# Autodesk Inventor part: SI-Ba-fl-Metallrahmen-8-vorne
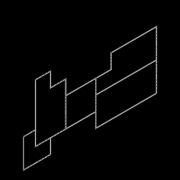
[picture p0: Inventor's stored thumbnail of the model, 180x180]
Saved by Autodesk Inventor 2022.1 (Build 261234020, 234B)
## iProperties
Created: 2021-12
Part Number: SI-Ba-fl-Metallrahmen-8-vorne
Material: Generisch
Document SubType Name: Modeling
Designer: Ruhl
Density: 1 g/cm^3
Appearance: Vorgabe
Author: Ruhl
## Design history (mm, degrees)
sketch "Skizze1"
  geometry: L1 (0, 0)-(-412, 0); L2 (-412, 0)-(-412, 210); L3 (-412, 210)-(-1052, 210); L4 (-1052, 210)-(-1052, 0); L5 (-1052, 0)-(-1952, 0); L6 (-1952, 0)-(-1952, 860); L7 (-1952, 860)-(-1272, 860); L8 (-1272, 860)-(-1272, 650); L9 (-1272, 650)-(-632, 650); L10 (-632, 650)-(-632, 860); L11 (-632, 860)-(-412, 860); L12 (-412, 860)-(-412, 1070); L13 (-412, 1070)-(-172, 1070); L14 (-172, 1070)-(-172, 440); L15 (-172, 440)-(0, 440); L16 (0, 440)-(0, 0); L17 (-192, 420)-(-192, 1050); L18 (-192, 1050)-(-392, 1050); L19 (-392, 1050)-(-392, 840); L20 (-392, 840)-(-612, 840); L21 (-612, 840)-(-612, 630); L22 (-612, 630)-(-1292, 630); L23 (-1292, 630)-(-1292, 840); L24 (-1292, 840)-(-1932, 840); L25 (-1932, 840)-(-1932, 20); L26 (-1932, 20)-(-1072, 20); L27 (-1072, 20)-(-1072, 230); L28 (-1072, 230)-(-392, 230); L29 (-392, 230)-(-392, 20); L30 (-392, 20)-(-15, 20); L31 (-15, 420)-(-192, 420); L32 (-15, 420)-(-15, 20); L33 (-392, 230)-(-192, 230); L34 (-192, 230)-(-192, 420); L35 (-1072, 230)-(-1052, 230); L36 (-1052, 230)-(-1052, 630); L37 (-1052, 630)-(-1072, 630); L38 (-1072, 630)-(-1072, 230); L39 (-192, 630)-(-192, 650); L40 (-612, 650)-(-612, 630); L41 (-1072, 420)-(-1932, 420); L42 (-1932, 420)-(-1932, 440); L43 (-1932, 440)-(-1072, 440); L44 (-1072, 440)-(-1072, 420); L45 (-172, 420)-(-172, 210); L46 (-172, 210)-(-392, 210); L47 (-612, 630)-(-632, 630); L48 (-632, 630)-(-632, 230); L49 (-632, 230)-(-612, 230); L50 (-612, 230)-(-612, 630); 15 further points
  constraints: 100 end point, 34 perpendicular, 10 collinear, 7 parallel, 5 horizontal, 2 midpoint, 1 coincident, 1 vertical, 14 other
  dimensions: "d0" = 900 distance of L4.end L5.end; "d1" = 210 distance of L3.end L4.end; "d2" = 640 distance of L2.end L3.end; "d3" = 412 distance of L1.start L1.end; "d4" = 860 distance of L5.end L6.end; "d5" = 680 distance of L6.end L7.end; "d6" = 210 distance of L7.end L8.end; "d7" = 210 distance of L11.end L12.end; "d8" = 240 distance of L12.end L13.end; "d9" = 440 distance of L15.end L1.start; "d10" = 220 distance of L10.end L11.end; "d11" = 640 distance of L8.end L9.end; "d12" = 20 distance between parallel lines of L14 L17; "d13" = 20 distance between parallel lines of L15 L31; "d14" = 15 distance between parallel lines of L16 L32; "d15" = 20 distance of L41.end L42.end; "d18" = 20 distance between parallel lines of L34 L45; "d19" = 20 distance of L49.end L48.end
extrude "Extrusion1" new body sketch "Skizze1" distance "d16" = 2; taper "d17" = 0 deg
sketch "Skizze2" dims "d42" = 10, "d49" = 10, "d56" = 10, "d75" = 10, "d82" = 10, "d128" = 30
  geometry: L1 (172, -1070)-(412, -1070) reference; L2 (1272, -860)-(1952, -860) reference; L3 (1952, -860)-(1952, 0) reference; L4 (1072, -20)-(1932, -20) reference; L5 (1932, -420)-(1072, -420) reference; L6 (612, -230)-(612, -840) reference; L7 (392, -840)-(392, -1050) reference; L8 (192, -1050)-(192, -230) reference; L9 (1072, -440)-(1932, -440) reference; L10 (1932, -840)-(1292, -840) reference; L11 (172, -420)-(15, -420) reference; L12 (15, -420)-(15, -20) reference; L13 (15, -20)-(392, -20) reference; L14 (392, -20)-(392, -210) reference; 68 further points
  constraints: 16 horizontal alignment, 15 vertical alignment, 3 horizontal, 2 vertical, 32 other
  dimensions: "d20" = 10 distance from line of L3 point (1942, -806.5); "d21" = 33.5 distance from line of point (1942, -806.5) L10; "d22" = 41 distance of point (1942, -765.5) point (1942, -806.5); "d23" = 41 distance of point (1942, -724.5) point (1942, -765.5); "d24" = 41 distance of point (1942, -683.5) point (1942, -724.5); "d25" = 33.5 distance from line of point (1942, -473.5) L9; "d26" = 41 distance of point (1942, -514.5) point (1942, -473.5); "d27" = 41 distance of point (1942, -555.5) point (1942, -514.5); "d28" = 41 distance of point (1942, -555.5) point (1942, -596.5); "d29" = 33.5 distance from line of point (1942, -386.5) L5; "d30" = 41 distance of point (1942, -345.5) point (1942, -386.5); "d31" = 41 distance of point (1942, -304.5) point (1942, -345.5); "d32" = 41 distance of point (1942, -263.5) point (1942, -304.5); "d33" = 33.5 distance from line of L4 point (1942, -53.5); "d34" = 41 distance of point (1942, -94.5) point (1942, -53.5); "d35" = 41 distance of point (1942, -94.5) point (1942, -135.5); "d36" = 41 distance of point (1942, -135.5) point (1942, -176.5); "d39" = 660 distance of point (1942, -683.5) point (1282, -683.5); "d46" = 880 distance of point (1942, -53.5) point (1062, -53.5); "d53" = 1320 distance of point (1942, -263.5) point (622, -263.5); "d58" = 10 distance from line of L1 point (356.5, -1060); "d59" = 35.5 distance from line of L7 point (356.5, -1060); "d60" = 43 distance of point (313.5, -1060) point (356.5, -1060); "d61" = 43 distance of point (270.5, -1060) point (313.5, -1060); "d62" = 43 distance of point (227.5, -1060) point (270.5, -1060); "d63" = 35.5 distance from line of L6 point (576.5, -850.032); "d64" = 43 distance of point (533.5, -850.032) point (576.5, -850.032); "d65" = 43 distance of point (490.5, -850.032) point (533.5, -850.032); "d66" = 43 distance of point (447.5, -850.032) point (490.5, -850.032); "d67" = 35.5 distance from line of L12 point (50.5, -430); "d68" = 43 distance of point (93.5, -430) point (50.5, -430); "d69" = 10 distance from line of L11 point (50.5, -430); "d72" = 630 distance of point (447.5, -850.032) point (447.5, -220.032); "d79" = 840 distance of point (227.5, -1060) point (227.5, -220); "d84" = 10 distance from line of L13 point (356.5, -10); "d85" = 35.5 distance from line of L14 point (356.5, -10); "d86" = 43 distance of point (313.5, -10) point (356.5, -10); "d87" = 43 distance of point (270.5, -10) point (313.5, -10); "d88" = 43 distance of point (227.5, -10) point (270.5, -10); "d89" = 35.5 distance from line of L12 point (50.5, -10); "d90" = 43 distance of point (93.5, -10) point (50.5, -10); "d140" = 43 distance of point (7.5, -430) point (50.5, -430); "d141" = 43 distance of point (7.5, -10) point (50.5, -10); "d142" = 43 distance of point (93.5, -430) point (136.5, -430); "d143" = 43 distance of point (93.5, -10) point (136.5, -10)
hole "Bohrung1" sketch "Skizze2" diameter "d91" = 4; stored, may be unused: countersink angle "d95" = 90 deg, drill point angle "d97" = 118 deg; dims "d92" = 6, "d93" = 8, "d94" = 2, "d96" = 8
sketch "Skizze3"
  geometry: L1 (0, 440)-(172, 440) reference; L2 (0, 0)-(0, 440) reference; L3 (412, 0)-(0, 0) reference; L4 (412, 210)-(412, 0) reference; L5 (1052, 210)-(412, 210) reference; L6 (1052, 0)-(1052, 210) reference; L7 (1952, 0)-(1052, 0) reference; L8 (1952, 860)-(1952, 0) reference; L9 (1272, 860)-(1952, 860) reference; L10 (1272, 650)-(1272, 860) reference; L11 (632, 650)-(1272, 650) reference; L12 (412, 1070)-(412, 860) reference; L13 (172, 1070)-(412, 1070) reference; L14 (172, 440)-(172, 1070) reference; L15 (1072, 420)-(1072, 20) reference; L16 (1932, 420)-(1072, 420) reference; L17 (632, 630)-(632, 230) reference; L18 (1052, 230)-(1052, 630) reference; L19 (1072, 440)-(1932, 440) reference; L20 (172, 210)-(172, 420) reference; L21 (392, 210)-(172, 210) reference; L22 (632, 860)-(632, 650) reference; L23 (412, 860)-(632, 860) reference; 18 further points
  constraints: 1 midpoint
  dimensions: "d98" = 10 distance from line of L13 point (182, 1060); "d99" = 10 distance from line of L14 point (182, 1060); "d100" = 10 distance from line of L13 point (402, 1060); "d101" = 10 distance from line of L12 point (402, 1060); "d102" = 10 distance from line of point (622, 640) L17; "d103" = 10 distance from line of L11 point (622, 640); "d104" = 10 distance from line of L11 point (1062, 640); "d105" = 10 distance from line of L18 point (1062, 640); "d106" = 10 distance from line of L9 point (1282, 850); "d107" = 10 distance from line of L10 point (1282, 850); "d108" = 10 distance from line of L8 point (1942, 850); "d109" = 10 distance from line of L9 point (1942, 850); "d110" = 10 distance from line of L8 point (1942, 430); "d111" = 10 distance from line of L16 point (1942, 430); "d112" = 10 distance from line of L8 point (1942, 10); "d113" = 10 distance from line of L7 point (1942, 10); "d114" = 10 distance from line of L6 point (1062, 10); "d115" = 10 distance from line of L7 point (1062, 10); "d116" = 10 distance of point (1072, 220) point (1062, 220); "d117" = 10 distance from line of L5 point (1062, 220); "d118" = 10 distance from line of point (1062, 430) L19; "d119" = 10 distance from line of L18 point (1062, 430); "d120" = 10 distance from line of L5 point (622, 220); "d121" = 10 distance from line of L17 point (622, 220); "d122" = 10 distance from line of L20 point (182, 220); "d123" = 10 distance from line of L21 point (182, 220); "d124" = 10 distance from line of L3 point (402, 10); "d126" = 10 distance from line of L4 point (402, 10); "d127" = 10 distance from line of L1 point (30, 430); "d128" = 30 distance from line of L2 point (30, 430); "d129" = 10 distance from line of L3 point (30, 10); "d130" = 30 distance from line of L2 point (30, 10); "d138" = 10 distance from line of L23 point (622, 850); "d139" = 10 distance from line of L22 point (622, 850)
hole "Bohrung2" sketch "Skizze3" at (1282, 850), (1942, 850), (1062, 430), (1942, 430), (1942, 10), (1062, 10), (1062, 640), (1062, 220), (622, 220), (622, 640), (402, 1060), (182, 1060)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 diameter "d131" = 4; stored, may be unused: countersink angle "d135" = 90 deg, drill point angle "d137" = 118 deg; dims "d132" = 6, "d133" = 8, "d134" = 2, "d136" = 8
node "Volumenkörper1"
